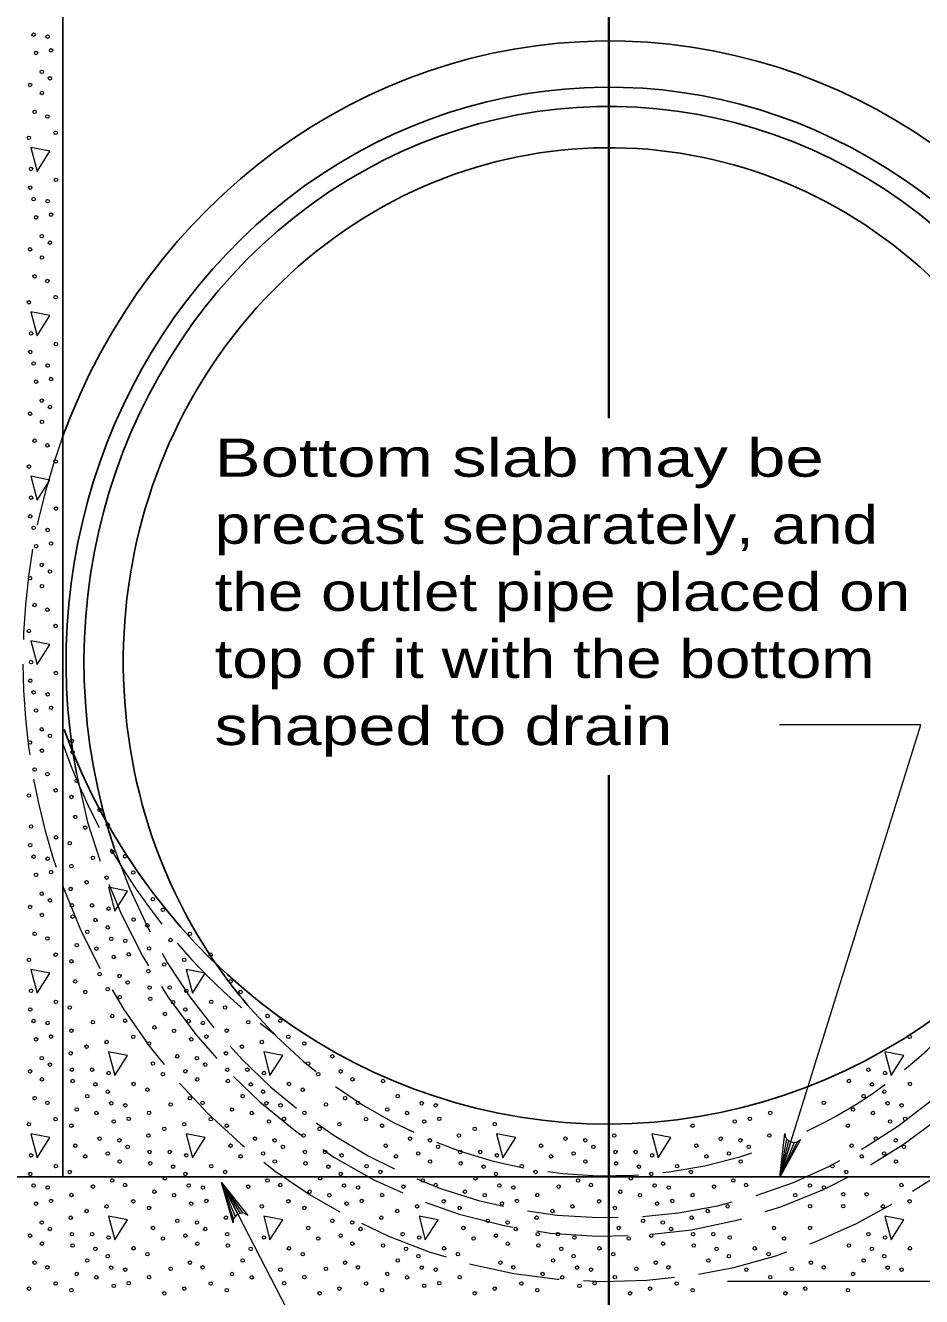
# Model space of a CAD drawing. Extents: x 1329.9 to 1363.9, y 715.5 to 737.5.
# Drawn here: x 1333.29 to 1336.95, y 718.65 to 723.85 of the extents above; entities that cross this region are included whole.
import ezdxf

# ---------------------------------------------------------------- set-up
doc = ezdxf.new("R2010")
doc.units = 0
doc.header["$LTSCALE"] = 0.062
doc.linetypes.add('LONG_DASHED', pattern=[7.5, 6, -1.5])
doc.layers.add('1', color=7, linetype='Continuous', lineweight=13)

msp = doc.modelspace()

# ---------------------------------------------------------------- linework, layer by layer
at = {"layer": '1', "lineweight": 25}
for p, q in [((1333.43842, 726.04008), (1333.43842, 720.98492)), ((1333.43842, 720.98492), (1333.43842, 719.143)), ((1332.86792, 719.143), (1338.4845, 719.143))]:
    msp.add_line(p, q, dxfattribs=at)
at = {"layer": '1', "lineweight": 35}
for p, q in [((1335.66942, 724.84575), (1335.66942, 722.24233)), ((1335.66942, 720.78442), (1335.66942, 717.76983))]:
    msp.add_line(p, q, dxfattribs=at)
at = {"layer": '1'}
for p, q in [((1336.87467, 719.63892), (1336.79675, 719.65408)), ((1336.39467, 719.2995), (1336.36808, 719.14133)), ((1336.40317, 719.29058), (1336.36808, 719.14133)), ((1336.413, 719.28525), (1336.36808, 719.14133)), ((1336.43825, 719.28517), (1336.36808, 719.14133)), ((1336.427, 719.283), (1336.36808, 719.14133)), ((1334.1535, 718.99008), (1334.08708, 719.11958)), ((1334.14258, 718.98142), (1334.08708, 719.11958)), ((1334.13642, 718.97175), (1334.08708, 719.11958)), ((1334.16383, 718.99358), (1334.08708, 719.11958)), ((1334.17558, 718.99383), (1334.08708, 719.11958)), ((1338.85383, 718.71467), (1336.15375, 718.71467))]:
    msp.add_line(p, q, dxfattribs=at)
for points in [[(1333.30758, 723.34817), (1333.33325, 723.25083), (1333.3855, 723.333)], [(1333.30758, 722.6765), (1333.33325, 722.57917), (1333.3855, 722.66133)], [(1333.30758, 722.00483), (1333.33325, 721.90758), (1333.3855, 721.98975)], [(1333.30758, 721.33317), (1333.33325, 721.23583), (1333.3855, 721.318)], [(1333.62483, 720.32575), (1333.6505, 720.22833), (1333.70275, 720.3105)], [(1333.30758, 719.98992), (1333.33325, 719.89258), (1333.3855, 719.97475)], [(1333.94208, 719.98992), (1333.96767, 719.89258), (1334.01992, 719.97475)], [(1333.62483, 719.65408), (1333.6505, 719.55675), (1333.70275, 719.63892)], [(1334.25917, 719.65408), (1334.28483, 719.55675), (1334.33708, 719.63892)], [(1333.30758, 719.31825), (1333.33325, 719.22092), (1333.3855, 719.30317)], [(1333.94208, 719.31825), (1333.96767, 719.22092), (1334.01992, 719.30317)], [(1335.21083, 719.31825), (1335.23642, 719.22092), (1335.28867, 719.30317)], [(1335.84525, 719.31825), (1335.87092, 719.22092), (1335.92308, 719.30317)], [(1333.62483, 718.9825), (1333.6505, 718.88517), (1333.70275, 718.96725)], [(1334.25917, 718.9825), (1334.28483, 718.88517), (1334.33708, 718.96725)], [(1334.89367, 718.9825), (1334.91933, 718.88517), (1334.9715, 718.96725)], [(1336.79675, 718.9825), (1336.82242, 718.88517), (1336.87467, 718.96725)]]:
    msp.add_lwpolyline(points, close=True, dxfattribs=at)
for points in [[(1336.36808, 719.14133), (1336.94458, 720.9895), (1336.36617, 720.9895)], [(1336.79675, 719.65408), (1336.82242, 719.55675), (1336.87467, 719.63892)], [(1336.45225, 719.2955), (1336.36808, 719.14133), (1336.38775, 719.31967)], [(1334.13392, 718.95458), (1334.08708, 719.11958), (1334.19375, 718.98525)], [(1334.08708, 719.11958), (1334.82208, 717.69408), (1334.27158, 717.69408)]]:
    msp.add_lwpolyline(points, dxfattribs=at)
msp.add_arc((1334.17008, 718.95785), 0.03631, 49.23268, 185.0588, dxfattribs=at)
for centre in [(1333.31883, 723.80906), (1333.37619, 723.80083), (1333.32904, 723.73468), (1333.39073, 723.74559), (1333.35224, 723.6576), (1333.38592, 723.63102), (1333.30482, 723.60382), (1333.35309, 723.57085), (1333.32312, 723.49378), (1333.37535, 723.47475), (1333.29996, 723.38766), (1333.40871, 723.40854), (1333.30852, 723.26072), (1333.41045, 723.21628), (1333.30509, 723.18454), (1333.31883, 723.13741), (1333.37619, 723.12919), (1333.32904, 723.06303), (1333.39073, 723.07394), (1333.35224, 722.98596), (1333.38592, 722.95937), (1333.30482, 722.93217), (1333.35309, 722.8992), (1333.32312, 722.82213), (1333.37535, 722.8031), (1333.40871, 722.73689), (1333.29996, 722.71601), (1333.30852, 722.58907), (1333.41045, 722.54463), (1333.30509, 722.5129), (1333.31883, 722.46577), (1333.37619, 722.45754), (1333.32904, 722.39138), (1333.39073, 722.4023), (1333.35224, 722.31431), (1333.38592, 722.28773), (1333.30482, 722.26053), (1333.35309, 722.22756), (1333.32312, 722.15049), (1333.37535, 722.13146), (1333.40871, 722.06524), (1333.29996, 722.04437), (1333.30852, 721.91743), (1333.41045, 721.87299), (1333.30509, 721.84125), (1333.31883, 721.79412), (1333.37619, 721.7859), (1333.32904, 721.71974), (1333.39073, 721.73065), (1333.35224, 721.64267), (1333.38592, 721.61608), (1333.30482, 721.58888), (1333.35309, 721.55591), (1333.32312, 721.47884), (1333.37535, 721.45981), (1333.40871, 721.3936), (1333.29996, 721.37272), (1333.30852, 721.24578), (1333.41045, 721.20134), (1333.30509, 721.16961), (1333.31883, 721.12248), (1333.37619, 721.11425), (1333.32904, 721.04809), (1333.39073, 721.05901), (1333.35224, 720.97102), (1333.38592, 720.94444), (1333.47585, 720.92356), (1333.30482, 720.91723), (1333.35309, 720.88427), (1333.47838, 720.87733), (1333.32312, 720.8072), (1333.37535, 720.78817), (1333.40871, 720.72195), (1333.49525, 720.76096), (1333.29996, 720.70108), (1333.47384, 720.69475), (1333.48927, 720.61315), (1333.58861, 720.6422), (1333.30852, 720.57414), (1333.5304, 720.5696), (1333.62202, 720.58141), (1333.41045, 720.52969), (1333.46697, 720.50613), (1333.30509, 720.49796), (1333.31883, 720.45083), (1333.64031, 720.47137), (1333.69255, 720.45234), (1333.37619, 720.4426), (1333.47384, 720.41177), (1333.56149, 720.44602), (1333.32904, 720.37645), (1333.39073, 720.38736), (1333.61716, 720.36525), (1333.72591, 720.38613), (1333.35224, 720.29938), (1333.47072, 720.31902), (1333.53574, 720.34622), (1333.30482, 720.24559), (1333.38592, 720.27279), (1333.47585, 720.25191), (1333.55811, 720.25191), (1333.80647, 720.27732), (1333.35309, 720.21262), (1333.47838, 720.20568), (1333.5718, 720.19208), (1333.62572, 720.23831), (1333.72765, 720.19387), (1333.8476, 720.23378), (1333.53833, 720.144), (1333.62229, 720.16214), (1333.78416, 720.17031), (1333.32312, 720.13555), (1333.37535, 720.11652), (1333.49525, 720.08932), (1333.63603, 720.11501), (1333.69339, 720.10678), (1333.87869, 720.1102), (1333.95751, 720.13555), (1333.40871, 720.05031), (1333.57603, 720.0751), (1333.64624, 720.04062), (1333.70793, 720.05154), (1333.79104, 720.07594), (1334.0431, 720.05031), (1333.29996, 720.02943), (1333.47384, 720.02311), (1333.78792, 719.9832), (1333.85294, 720.0104), (1333.93436, 720.02943), (1333.48927, 719.9415), (1333.58861, 719.97055), (1333.66944, 719.96355), (1333.70312, 719.93697), (1334.12367, 719.9415), (1333.30852, 719.90249), (1333.5304, 719.89796), (1333.62202, 719.90977), (1333.79305, 719.91609), (1333.87531, 719.91609), (1333.94292, 719.90249), (1334.1648, 719.89796), (1333.41045, 719.85805), (1333.46697, 719.83449), (1333.67029, 719.8768), (1333.79558, 719.86986), (1333.889, 719.85626), (1334.04485, 719.85805), (1334.10136, 719.83449), (1333.30509, 719.82631), (1333.31883, 719.77919), (1333.64031, 719.79973), (1333.69255, 719.7807), (1333.85553, 719.80818), (1333.93949, 719.82631), (1333.95323, 719.77919), (1334.27471, 719.79973), (1334.32695, 719.7807), (1333.37619, 719.77096), (1333.47384, 719.74012), (1333.56149, 719.77437), (1333.81245, 719.7535), (1333.89323, 719.73928), (1334.01059, 719.77096), (1334.10824, 719.74012), (1334.19589, 719.77437), (1333.32904, 719.7048), (1333.39073, 719.71572), (1333.53574, 719.67458), (1333.61716, 719.69361), (1333.72591, 719.71449), (1333.79104, 719.68728), (1333.96343, 719.7048), (1334.02513, 719.71572), (1334.17014, 719.67458), (1334.25156, 719.69361), (1334.3603, 719.71449), (1334.42544, 719.68728), (1336.8979, 719.71449), (1333.35224, 719.62773), (1333.47072, 719.64738), (1333.90581, 719.63473), (1333.98664, 719.62773), (1334.10512, 719.64738), (1334.54021, 719.63473), (1333.30482, 719.57394), (1333.38592, 719.60114), (1333.47585, 719.58027), (1333.55811, 719.58027), (1333.80647, 719.60568), (1333.93922, 719.57394), (1334.02032, 719.60114), (1334.11025, 719.58027), (1334.19251, 719.58027), (1334.44087, 719.60568), (1334.57362, 719.57394), (1336.7301, 719.58027), (1333.35309, 719.54098), (1333.47838, 719.53404), (1333.5718, 719.52044), (1333.62572, 719.56667), (1333.72765, 719.52223), (1333.8476, 719.56213), (1333.98749, 719.54098), (1334.11278, 719.53404), (1334.2062, 719.52044), (1334.26012, 719.56667), (1334.36205, 719.52223), (1334.482, 719.56213), (1334.62189, 719.54098), (1334.74718, 719.53404), (1336.65038, 719.53404), (1336.74379, 719.52044), (1336.79772, 719.56667), (1336.89964, 719.52223), (1333.32312, 719.46391), (1333.53833, 719.47236), (1333.62229, 719.49049), (1333.78416, 719.49866), (1333.95751, 719.46391), (1334.17273, 719.47236), (1334.25669, 719.49049), (1334.41856, 719.49866), (1334.59191, 719.46391), (1334.80713, 719.47236), (1336.71033, 719.47236), (1336.79428, 719.49049), (1333.37535, 719.44488), (1333.49525, 719.41767), (1333.63603, 719.44336), (1333.69339, 719.43514), (1333.87869, 719.43855), (1334.00975, 719.44488), (1334.12965, 719.41767), (1334.27043, 719.44336), (1334.32779, 719.43514), (1334.51309, 719.43855), (1334.64414, 719.44488), (1334.76405, 719.41767), (1334.90483, 719.44336), (1334.96219, 719.43514), (1336.54734, 719.44488), (1336.66724, 719.41767), (1336.80803, 719.44336), (1336.86539, 719.43514), (1333.40871, 719.37866), (1333.57603, 719.40346), (1333.64624, 719.36898), (1333.70793, 719.37989), (1333.79104, 719.4043), (1334.0431, 719.37866), (1334.21043, 719.40346), (1334.28063, 719.36898), (1334.34233, 719.37989), (1334.42544, 719.4043), (1334.6775, 719.37866), (1334.84483, 719.40346), (1334.91503, 719.36898), (1334.97673, 719.37989), (1336.18383, 719.36898), (1336.24553, 719.37989), (1336.32863, 719.4043), (1336.74802, 719.40346), (1336.81823, 719.36898), (1336.87992, 719.37989), (1333.29996, 719.35779), (1333.47384, 719.35146), (1333.78792, 719.31155), (1333.85294, 719.33876), (1333.93436, 719.35779), (1334.10824, 719.35146), (1334.42232, 719.31155), (1334.48734, 719.33876), (1334.56876, 719.35779), (1334.74264, 719.35146), (1335.05672, 719.31155), (1335.12174, 719.33876), (1335.20316, 719.35779), (1335.69111, 719.31155), (1336.01143, 719.35146), (1336.32551, 719.31155), (1336.64583, 719.35146), (1333.48927, 719.26986), (1333.58861, 719.2989), (1333.66944, 719.29191), (1333.70312, 719.26532), (1334.12367, 719.26986), (1334.22301, 719.2989), (1334.30384, 719.29191), (1334.33752, 719.26532), (1334.75807, 719.26986), (1334.85741, 719.2989), (1334.93824, 719.29191), (1334.97192, 719.26532), (1335.39247, 719.26986), (1335.49181, 719.2989), (1335.57264, 719.29191), (1335.60632, 719.26532), (1336.02687, 719.26986), (1336.12621, 719.2989), (1336.20704, 719.29191), (1336.24071, 719.26532), (1336.66127, 719.26986), (1336.7606, 719.2989), (1336.84144, 719.29191), (1336.87511, 719.26532), (1333.30852, 719.23084), (1333.5304, 719.22631), (1333.62202, 719.23812), (1333.67029, 719.20515), (1333.79305, 719.24445), (1333.87531, 719.24445), (1333.94292, 719.23084), (1334.1648, 719.22631), (1334.25642, 719.23812), (1334.30469, 719.20515), (1334.42744, 719.24445), (1334.50971, 719.24445), (1334.57732, 719.23084), (1334.7992, 719.22631), (1334.89082, 719.23812), (1334.93909, 719.20515), (1335.06184, 719.24445), (1335.1441, 719.24445), (1335.21172, 719.23084), (1335.4336, 719.22631), (1335.52522, 719.23812), (1335.57349, 719.20515), (1335.69624, 719.24445), (1335.7785, 719.24445), (1335.84612, 719.23084), (1336.068, 719.22631), (1336.15962, 719.23812), (1336.20788, 719.20515), (1336.7024, 719.22631), (1336.79402, 719.23812), (1336.84228, 719.20515), (1333.30509, 719.15467), (1333.41045, 719.1864), (1333.46697, 719.16284), (1333.79558, 719.19821), (1333.889, 719.18461), (1333.93949, 719.15467), (1334.04485, 719.1864), (1334.10136, 719.16284), (1334.42998, 719.19821), (1334.5234, 719.18461), (1334.57389, 719.15467), (1334.67925, 719.1864), (1334.73576, 719.16284), (1335.06438, 719.19821), (1335.1578, 719.18461), (1335.20828, 719.15467), (1335.31365, 719.1864), (1335.37016, 719.16284), (1335.69878, 719.19821), (1335.79219, 719.18461), (1335.84268, 719.15467), (1335.94805, 719.1864), (1336.00456, 719.16284), (1336.58244, 719.1864), (1336.63896, 719.16284), (1333.31883, 719.10754), (1333.56149, 719.10273), (1333.64031, 719.12808), (1333.69255, 719.10905), (1333.85553, 719.13653), (1333.95323, 719.10754), (1334.19589, 719.10273), (1334.27471, 719.12808), (1334.32695, 719.10905), (1334.48993, 719.13653), (1334.58763, 719.10754), (1334.83029, 719.10273), (1334.90911, 719.12808), (1334.96134, 719.10905), (1335.12433, 719.13653), (1335.22203, 719.10754), (1335.46469, 719.10273), (1335.54351, 719.12808), (1335.59574, 719.10905), (1335.75873, 719.13653), (1335.85643, 719.10754), (1336.09909, 719.10273), (1336.17791, 719.12808), (1336.23014, 719.10905), (1336.49083, 719.10754), (1336.86454, 719.10905), (1333.37619, 719.09931), (1333.47384, 719.06847), (1333.81245, 719.08185), (1333.89323, 719.06763), (1334.01059, 719.09931), (1334.44685, 719.08185), (1334.52763, 719.06763), (1334.64499, 719.09931), (1334.74264, 719.06847), (1335.08125, 719.08185), (1335.16203, 719.06763), (1335.27939, 719.09931), (1335.37703, 719.06847), (1335.71564, 719.08185), (1335.79642, 719.06763), (1335.91379, 719.09931), (1336.01143, 719.06847), (1336.43082, 719.06763), (1336.54819, 719.09931), (1336.6268, 719.07127), (1336.72234, 719.07127), (1333.32904, 719.03316), (1333.39073, 719.04407), (1333.53574, 719.00293), (1333.61716, 719.02196), (1333.72591, 719.04284), (1333.79104, 719.01564), (1333.96343, 719.03316), (1334.02513, 719.04407), (1334.25156, 719.02196), (1334.3603, 719.04284), (1334.42544, 719.01564), (1334.59783, 719.03316), (1334.65953, 719.04407), (1334.80454, 719.00293), (1334.88596, 719.02196), (1334.9947, 719.04284), (1335.05983, 719.01564), (1335.23223, 719.03316), (1335.29393, 719.04407), (1335.43894, 719.00293), (1335.52036, 719.02196), (1335.6291, 719.04284), (1335.69423, 719.01564), (1335.86663, 719.03316), (1335.92833, 719.04407), (1336.07334, 719.00293), (1336.15475, 719.02196), (1336.49171, 719.02295), (1336.6268, 719.02295), (1336.78915, 719.02196), (1336.8979, 719.04284), (1333.35224, 718.95609), (1333.47072, 718.97573), (1333.90581, 718.96308), (1333.98664, 718.95609), (1334.10512, 718.97573), (1334.54021, 718.96308), (1334.62104, 718.95609), (1334.73952, 718.97573), (1335.17461, 718.96308), (1335.25544, 718.95609), (1335.37391, 718.97573), (1335.80901, 718.96308), (1335.88984, 718.95609), (1336.00831, 718.97573), (1333.30482, 718.9023), (1333.38592, 718.9295), (1333.47585, 718.90862), (1333.55811, 718.90862), (1333.62572, 718.89502), (1333.80647, 718.93403), (1333.93922, 718.9023), (1334.02032, 718.9295), (1334.11025, 718.90862), (1334.26012, 718.89502), (1334.44087, 718.93403), (1334.57362, 718.9023), (1334.65472, 718.9295), (1334.8269, 718.90862), (1334.89452, 718.89502), (1335.07527, 718.93403), (1335.20802, 718.9023), (1335.28912, 718.9295), (1335.37904, 718.90862), (1335.4613, 718.90862), (1335.52892, 718.89502), (1335.70967, 718.93403), (1335.84242, 718.9023), (1335.92352, 718.9295), (1336.01344, 718.90862), (1336.0957, 718.90862), (1336.16332, 718.89502), (1336.34407, 718.93403), (1336.49171, 718.93403), (1336.7301, 718.90862), (1336.79772, 718.89502), (1333.35309, 718.86933), (1333.47838, 718.86239), (1333.5718, 718.84879), (1333.72765, 718.85058), (1333.8476, 718.89049), (1333.98749, 718.86933), (1334.11278, 718.86239), (1334.2062, 718.84879), (1334.36205, 718.85058), (1334.482, 718.89049), (1334.62189, 718.86933), (1334.74718, 718.86239), (1334.8406, 718.84879), (1334.99645, 718.85058), (1335.1164, 718.89049), (1335.25629, 718.86933), (1335.38158, 718.86239), (1335.475, 718.84879), (1335.63085, 718.85058), (1335.7508, 718.89049), (1335.89069, 718.86933), (1336.01598, 718.86239), (1336.10939, 718.84879), (1336.26524, 718.85058), (1336.3852, 718.89049), (1336.65038, 718.86239), (1336.74379, 718.84879), (1336.89964, 718.85058), (1333.32312, 718.79226), (1333.53833, 718.80071), (1333.62229, 718.81885), (1333.78416, 718.82702), (1333.95751, 718.79226), (1334.17273, 718.80071), (1334.41856, 718.82702), (1334.59191, 718.79226), (1334.80713, 718.80071), (1334.89108, 718.81885), (1335.05296, 718.82702), (1335.22631, 718.79226), (1335.44153, 718.80071), (1335.52548, 718.81885), (1335.68736, 718.82702), (1335.86071, 718.79226), (1336.07593, 718.80071), (1336.15988, 718.81885), (1336.32176, 718.82702), (1336.49511, 718.79226), (1336.71033, 718.80071), (1336.79428, 718.81885), (1333.37535, 718.77323), (1333.49525, 718.74603), (1333.63603, 718.77172), (1333.69339, 718.76349), (1333.87869, 718.76691), (1334.00975, 718.77323), (1334.12965, 718.74603), (1334.32779, 718.76349), (1334.51309, 718.76691), (1334.64414, 718.77323), (1334.76405, 718.74603), (1334.90483, 718.77172), (1334.96219, 718.76349), (1335.27854, 718.77323), (1335.39844, 718.74603), (1335.53923, 718.77172), (1335.59659, 718.76349), (1335.78189, 718.76691), (1335.91294, 718.77323), (1336.23099, 718.76349), (1336.41628, 718.76691), (1336.54734, 718.77323), (1336.66724, 718.74603), (1336.80803, 718.77172), (1336.86539, 718.76349), (1333.29996, 718.68614), (1333.40871, 718.70702), (1333.57603, 718.73181), (1333.64624, 718.69733), (1333.70793, 718.70825), (1333.79104, 718.73265), (1333.93436, 718.68614), (1334.0431, 718.70702), (1334.21043, 718.73181), (1334.34233, 718.70825), (1334.42544, 718.73265), (1334.56876, 718.68614), (1334.6775, 718.70702), (1334.84483, 718.73181), (1334.91503, 718.69733), (1334.97673, 718.70825), (1335.05983, 718.73265), (1335.20316, 718.68614), (1335.3119, 718.70702), (1335.47922, 718.73181), (1335.54943, 718.69733), (1335.61113, 718.70825), (1335.69423, 718.73265), (1335.83755, 718.68614), (1335.9463, 718.70702), (1336.32863, 718.73265), (1336.47195, 718.68614), (1333.47384, 718.67982), (1333.85294, 718.66711), (1334.10824, 718.67982), (1334.48734, 718.66711), (1334.74264, 718.67982), (1335.12174, 718.66711), (1335.37703, 718.67982), (1335.75614, 718.66711), (1336.01143, 718.67982), (1336.39054, 718.66711), (1336.64583, 718.67982)]:
    msp.add_ellipse(centre, major_axis=(0, 0.00718), ratio=0.944544, dxfattribs=at)
at = {"layer": '1', "lineweight": 25}
for centre, major_axis, start_param, end_param in [((1335.66941, 721.24918), (0, -2.53448), 1.9607306, 4.343612), ((1335.66941, 721.24721), (0, -2.34775), 1.3944021, 4.9078414), ((1335.66941, 721.24578), (0, 2.27026), 4.4130472, 8.1227679), ((1335.66941, 721.24721), (0, 2.1004), 4.0791732, 8.4607413), ((1335.66522, 721.87991), (0, -2.52169), 5.0813574, 7.4910277)]:
    msp.add_ellipse(centre, major_axis=major_axis, ratio=0.944544, start_param=start_param, end_param=end_param, dxfattribs=at)
at = {"layer": '1', "linetype": 'LONG_DASHED'}
for centre, major_axis, start_param, end_param in [((1335.66941, 721.24918), (0, -2.53448), 4.343612, 5.0823137), ((1335.68077, 721.79836), (0, -2.53448), 5.0699775, 5.6726179), ((1335.66941, 721.24721), (0, -2.34775), 4.9078414, 7.6167139), ((1335.66941, 721.24578), (0, 2.27026), 1.91212, 4.328587), ((1335.66941, 721.24918), (0, -2.53448), 5.0823137, 7.4612989), ((1335.66941, 721.24721), (0, 2.1004), 2.3113692, 3.4903868), ((1335.66941, 721.24721), (0, 2.1004), 3.5617964, 3.9243143)]:
    msp.add_ellipse(centre, major_axis=major_axis, ratio=0.944544, start_param=start_param, end_param=end_param, dxfattribs=at)
at = {"layer": '1', "linetype": 'LONG_DASHED', "lineweight": 25}
for centre, major_axis, start_param, end_param in [((1335.66941, 721.24578), (0, 2.27026), 1.8395826, 1.91212), ((1335.66941, 721.24721), (0, 2.1004), 2.177556, 2.3113692)]:
    msp.add_ellipse(centre, major_axis=major_axis, ratio=0.944544, start_param=start_param, end_param=end_param, dxfattribs=at)
at = {"layer": '1'}
msp.add_ellipse((1336.42424, 719.3211), major_axis=(-0.01339, 0.03603), ratio=0.944544, start_param=1.2696525, end_param=3.6402657, dxfattribs=at)

# ---------------------------------------------------------------- texts
for s, width, p in [('Bottom slab may be', 1.35, (1334.05858, 722.00325)), ('precast separately, and', 1.25, (1334.05858, 721.72917)), ('the outlet pipe placed on', 1.25, (1334.05858, 721.45508)), ('top of it with the bottom', 1.25, (1334.05858, 721.181)), ('shaped to drain', 1.3, (1334.05858, 720.90692))]:
    msp.add_text(s, height=0.156, dxfattribs=dict(at, width=width)).set_placement(p)

doc.saveas('drawing.dxf')
